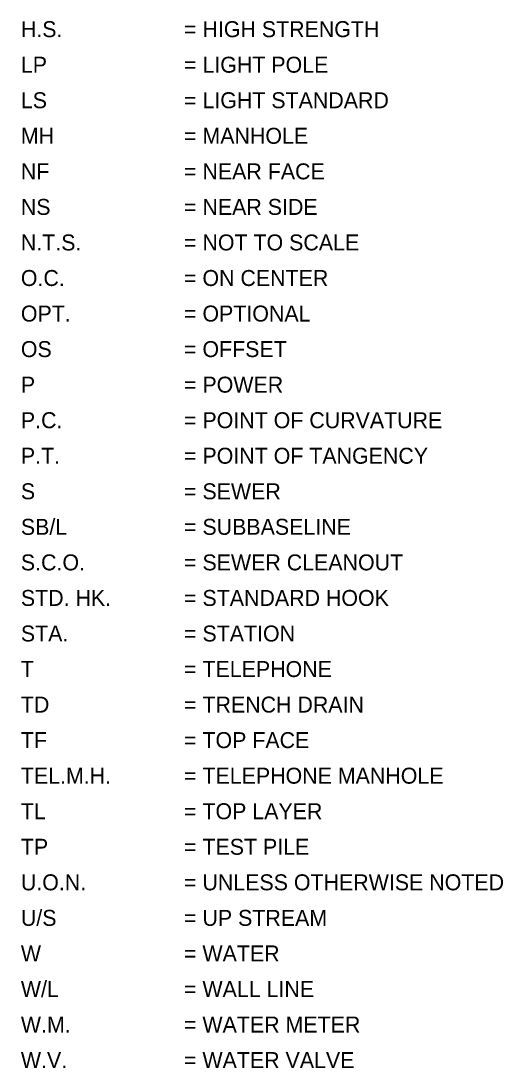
# Model space of a CAD drawing. Extents: x 22369.62 to 22376.4, y 22369.62 to 22372.46.
# Drawn here: x 22374.865 to 22375.217, y 22370.229 to 22370.996 of the extents above; entities that cross this region are included whole.
import ezdxf

# ---------------------------------------------------------------- set-up
doc = ezdxf.new("R2010")
doc.units = 0
doc.layers.add('Level 4', color=7, linetype='Continuous')

msp = doc.modelspace()

# ---------------------------------------------------------------- texts
at = {"layer": 'Level 4'}
for s, height, p in [('H.S.', 0.011698, (22374.86444, 22370.98426)), ('= HIGH STRENGTH', 0.0116979, (22374.98386, 22370.98426)), ('LP ', 0.011698, (22374.86444, 22370.95822)), ('= LIGHT POLE', 0.0116979, (22374.98386, 22370.95822)), ('LS', 0.011698, (22374.86444, 22370.93218)), ('= LIGHT STANDARD', 0.0116979, (22374.98386, 22370.93218)), ('MH ', 0.011698, (22374.86444, 22370.90613)), ('= MANHOLE', 0.011698, (22374.98386, 22370.90613)), ('NF', 0.011698, (22374.86444, 22370.88009)), ('= NEAR FACE', 0.0116979, (22374.98386, 22370.88009)), ('NS', 0.011698, (22374.86444, 22370.85405)), ('= NEAR SIDE', 0.0116979, (22374.98386, 22370.85405)), ('N.T.S.', 0.011698, (22374.86444, 22370.82801)), ('= NOT TO SCALE', 0.0116979, (22374.98386, 22370.82801)), ('O.C.', 0.011698, (22374.86444, 22370.80197)), ('= ON CENTER', 0.0116979, (22374.98386, 22370.80197)), ('OPT.', 0.011698, (22374.86444, 22370.77593)), ('= OPTIONAL', 0.011698, (22374.98386, 22370.77593)), ('OS', 0.011698, (22374.86444, 22370.74988)), ('= OFFSET', 0.011698, (22374.98386, 22370.74988)), ('P', 0.0117, (22374.86444, 22370.72384)), ('= POWER', 0.011698, (22374.98386, 22370.72384)), ('P.C.', 0.011698, (22374.86444, 22370.6978)), ('= POINT OF CURVATURE', 0.0116979, (22374.98386, 22370.6978)), ('P.T.', 0.011698, (22374.86444, 22370.67176)), ('= POINT OF TANGENCY', 0.0116979, (22374.98386, 22370.67176)), ('S', 0.0117, (22374.86444, 22370.64572)), ('= SEWER', 0.011698, (22374.98386, 22370.64572)), ('SB/L', 0.011698, (22374.86444, 22370.61968)), ('= SUBBASELINE', 0.0116979, (22374.98386, 22370.61968)), ('S.C.O.', 0.011698, (22374.86444, 22370.59363)), ('= SEWER CLEANOUT', 0.0116979, (22374.98386, 22370.59363)), ('STD. HK.', 0.011698, (22374.86444, 22370.56759)), ('= STANDARD HOOK', 0.0116979, (22374.98386, 22370.56759)), ('STA.', 0.011698, (22374.86444, 22370.54155)), ('= STATION', 0.011698, (22374.98386, 22370.54155)), ('T', 0.0117, (22374.86444, 22370.51551)), ('= TELEPHONE', 0.0116979, (22374.98386, 22370.51551)), ('TD', 0.011698, (22374.86444, 22370.48947)), ('= TRENCH DRAIN', 0.0116979, (22374.98386, 22370.48947)), ('TF', 0.011698, (22374.86444, 22370.46343)), ('= TOP FACE', 0.011698, (22374.98386, 22370.46343)), ('TEL.M.H. ', 0.011698, (22374.86444, 22370.43738)), ('= TELEPHONE MANHOLE', 0.0116979, (22374.98386, 22370.43738)), ('TL', 0.011698, (22374.86444, 22370.41134)), ('= TOP LAYER', 0.0116979, (22374.98386, 22370.41134)), ('TP', 0.011698, (22374.86444, 22370.3853)), ('= TEST PILE', 0.0116979, (22374.98386, 22370.3853)), ('U.O.N.', 0.011698, (22374.86444, 22370.35926)), ('= UNLESS OTHERWISE NOTED', 0.0116979, (22374.98386, 22370.35926)), ('U/S', 0.011698, (22374.86444, 22370.33322)), ('= UP STREAM', 0.0116979, (22374.98386, 22370.33322)), ('W ', 0.011698, (22374.86444, 22370.30718)), ('= WATER', 0.011698, (22374.98386, 22370.30718)), ('W/L', 0.011698, (22374.86444, 22370.28113)), ('= WALL LINE', 0.0116979, (22374.98386, 22370.28113)), ('W.M.', 0.011698, (22374.86444, 22370.25509)), ('= WATER METER', 0.0116979, (22374.98386, 22370.25509)), ('W.V.', 0.011698, (22374.86444, 22370.22905)), ('= WATER VALVE', 0.0116979, (22374.98386, 22370.22905))]:
    msp.add_text(s, height=height, dxfattribs=at).set_placement(p)

doc.saveas('drawing.dxf')
